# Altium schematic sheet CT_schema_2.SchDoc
size 313 x 200 mm
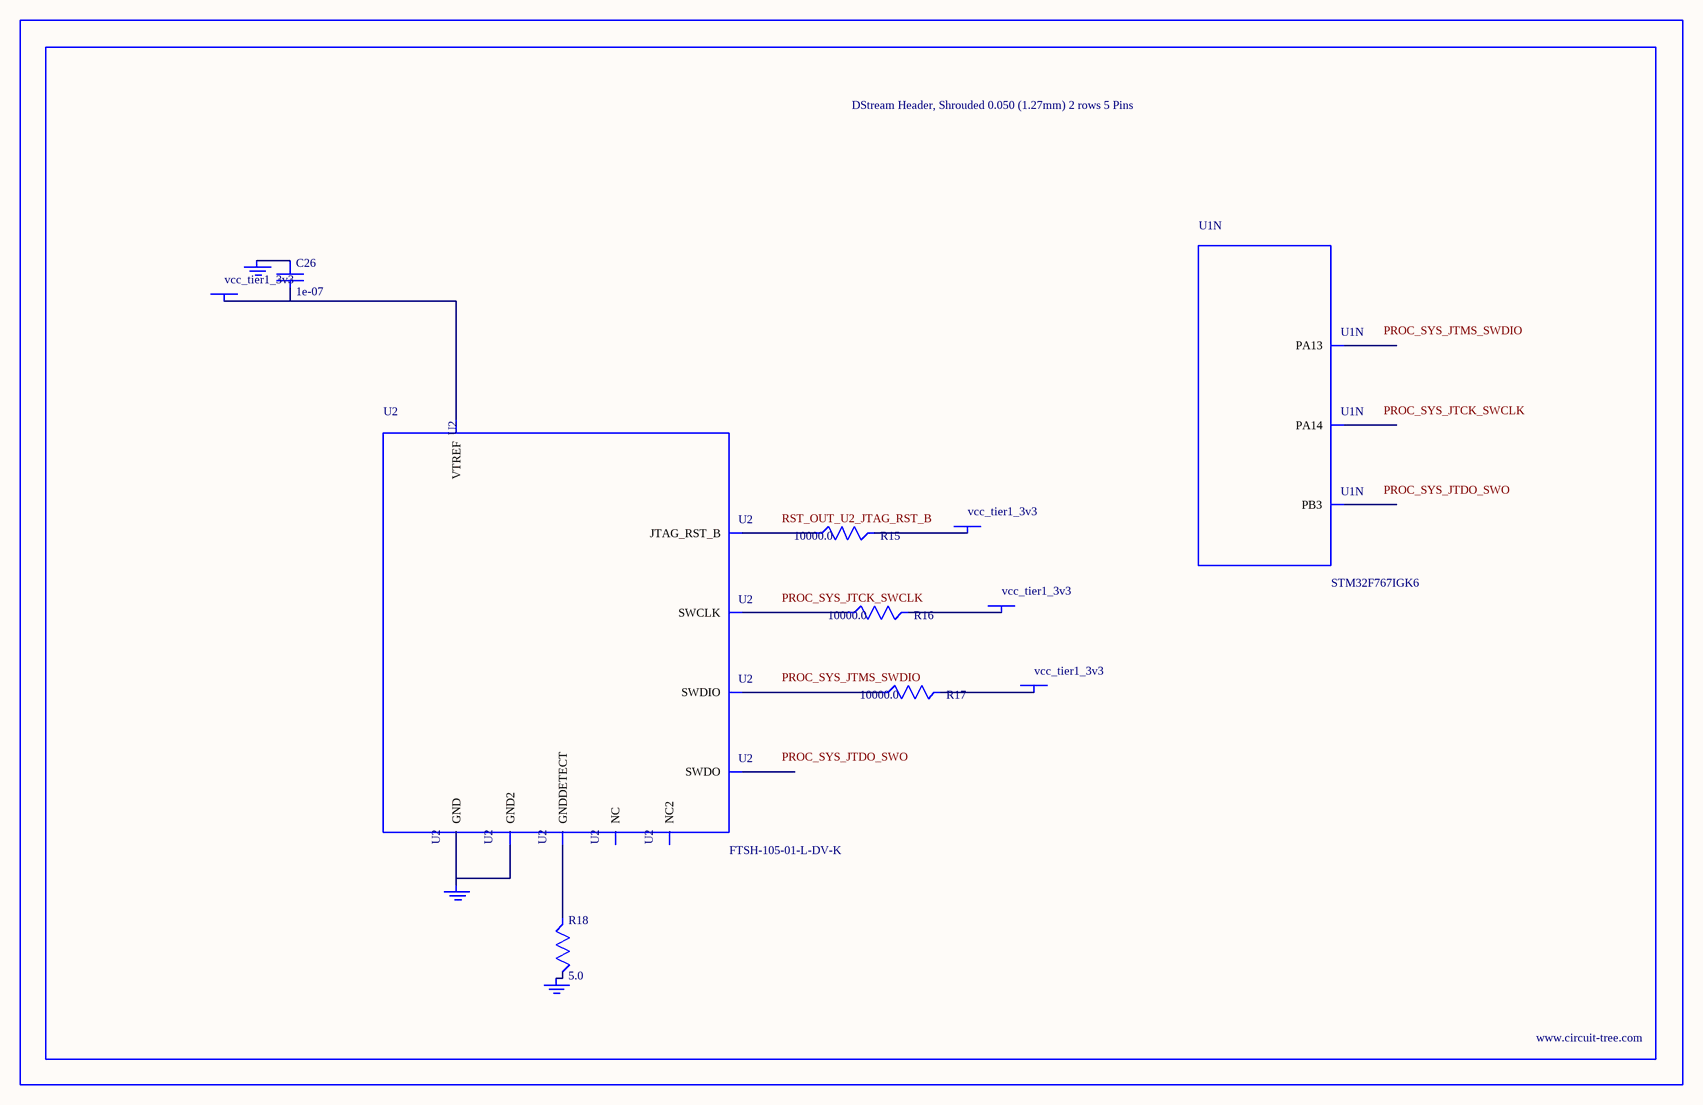
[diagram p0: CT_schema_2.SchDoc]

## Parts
BORDER1  (no value)
C26  1e-07  [C0402]
GND_INSTANCE_1_0  (no value)
GND_INSTANCE_1_1  (no value)
GND_INSTANCE_1_2  (no value)
POWER_INSTANCE_1_0  vcc_tier1_3v3
POWER_INSTANCE_1_1  vcc_tier1_3v3
POWER_INSTANCE_1_2  vcc_tier1_3v3
POWER_INSTANCE_1_3  vcc_tier1_3v3
R15  10000.0  [R0603]
R16  10000.0  [R0603]
R17  10000.0  [R0603]
R18  5.0  [R0603]
U1  STM32F767IGK6  [UFBGA176_25]  (part N of 16)
U2  FTSH-105-01-L-DV-K  [SAMTEC_FTSH-105-01-L-DV-K]

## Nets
NetC26_1: C26.1 GND_INSTANCE_1_0.0(GND)
NetC26_2: C26.2 POWER_INSTANCE_1_0.0(PWR) U2.1(VTREF)
NetGND_INSTANCE_1_1_0: GND_INSTANCE_1_1.0(GND) R18.2
NetGND_INSTANCE_1_2_0: GND_INSTANCE_1_2.0(GND) U2.3(GND) U2.5(GND2)
NetPOWER_INSTANCE_1_1_0: POWER_INSTANCE_1_1.0(PWR) R17.2
NetPOWER_INSTANCE_1_2_0: POWER_INSTANCE_1_2.0(PWR) R16.2
NetPOWER_INSTANCE_1_3_0: POWER_INSTANCE_1_3.0(PWR) R15.2
NetR15_1: R15.1 U2.10(JTAG_RST_B)
NetR16_1: R16.1 U2.4(SWCLK)
NetR17_1: R17.1 U2.2(SWDIO)
NetR18_1: R18.1 U2.9(GNDDETECT)

Not connected (* = marked no-connect by the designer): U1 A10(PB3) A14(PA14) A15(PA13); U2 6(SWDO) 7(NC) 8(NC2)

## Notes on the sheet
- Labels drawn without touching a wire or pin: PROC_SYS_JTCK_SWCLK, PROC_SYS_JTDO_SWO, PROC_SYS_JTMS_SWDIO, RST_OUT_U2_JTAG_RST_B

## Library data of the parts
BORDER1 = BORDER_PAGE1
C26 = C0402C104K3RACTU
GND_INSTANCE_1_0-GND_INSTANCE_1_2 = GND
POWER_INSTANCE_1_0-POWER_INSTANCE_1_3 = PWR
R15-R17 = RC0603JR-0710KL
R18 = ERJ-3GEYJ5R1V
